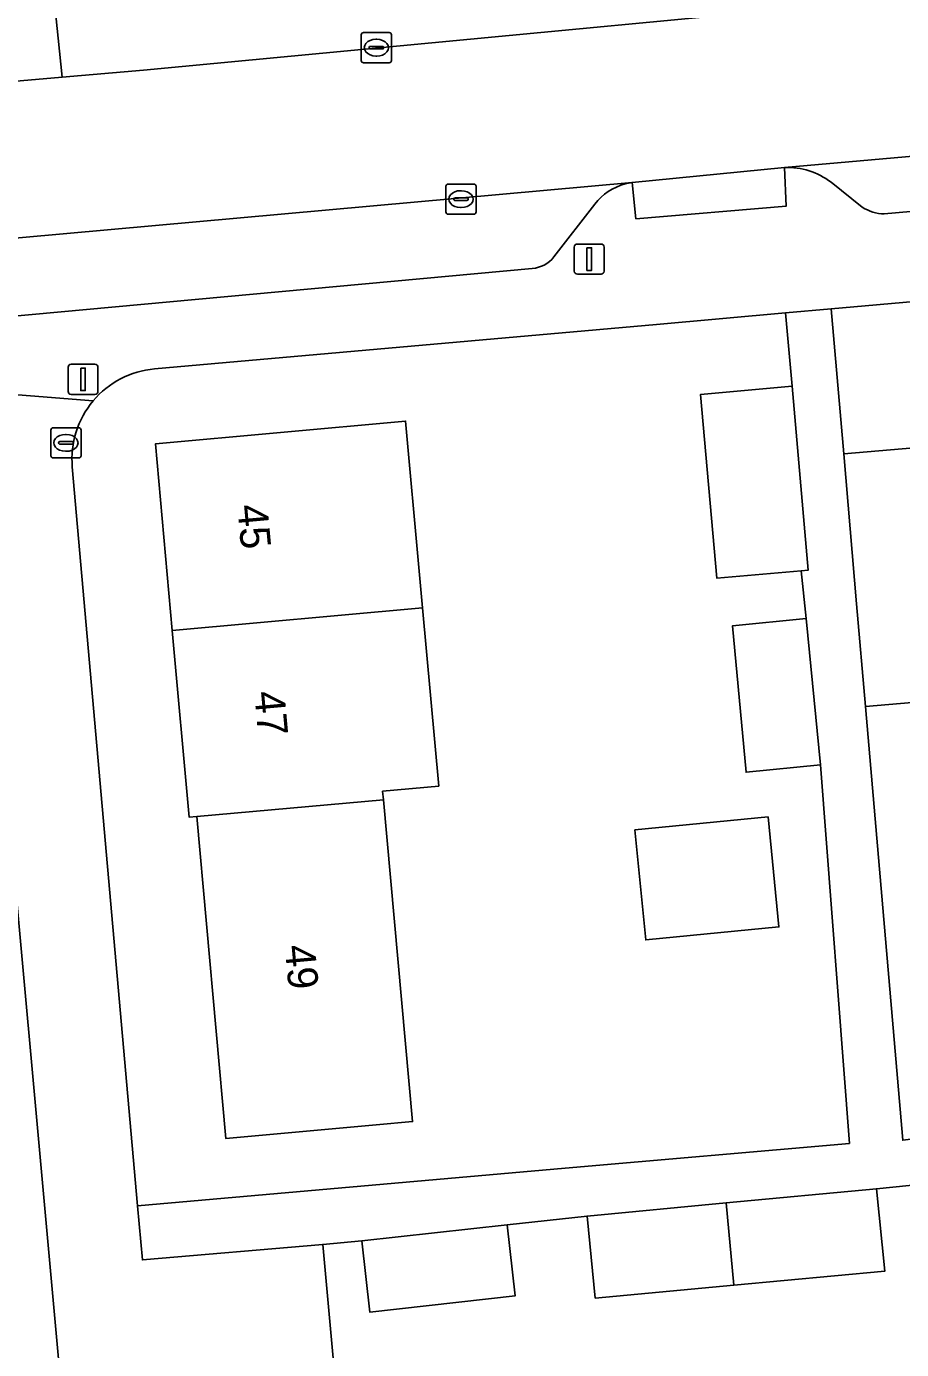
# Model space of a CAD drawing. Extents: x 160554 to 161248, y 385329 to 386506.
# Drawn here: x 160851.48 to 160880.52, y 385569.34 to 385613.21 of the extents above; entities that cross this region are included whole.
import ezdxf

# ---------------------------------------------------------------- set-up
doc = ezdxf.new("R2010")
doc.units = 0
for name, color, linetype in [('IMGEO_Erf', 7, 'Continuous'), ('IMGEO_Kolk', 7, 'Continuous'), ('IMGEO_Lichtmast', 7, 'Continuous'), ('IMGEO_Pand', 7, 'Continuous'), ('IMGEO_Pand_nummerreeks', 7, 'Continuous'), ('IMGEO_Parkeervlak_open', 7, 'Continuous'), ('IMGEO_Rijbaan_lokaal_open', 7, 'Continuous'), ('IMGEO_Voetpad_open', 7, 'Continuous')]:
    doc.layers.add(name, color=color, linetype=linetype)

msp = doc.modelspace()

# ---------------------------------------------------------------- linework, layer by layer
at = {"layer": 'IMGEO_Erf'}
for points in [[(160908.245, 385606.508), (160878.183, 385603.847), (160878.608, 385599.047), (160884.671, 385599.563)], [(160877.196, 385595.166), (160874.392, 385594.918), (160873.854, 385601.014), (160876.889, 385601.282), (160876.674, 385603.713), (160872.393, 385603.334), (160855.731, 385601.859)], [(160853.004, 385598.607), (160855.171, 385574.108), (160869.356, 385575.356), (160878.791, 385576.176), (160877.83, 385588.725), (160875.36, 385588.483), (160874.909, 385593.334), (160877.352, 385593.581), (160877.196, 385595.166)], [(160885.385, 385591.184), (160879.321, 385590.668), (160880.56, 385576.28)], [(160853.807, 385555.183), (160850.785, 385588.354)], [(160881.973, 385574.899), (160879.689, 385574.673), (160879.972, 385571.941), (160874.957, 385571.475), (160870.356, 385571.048), (160870.086, 385573.767), (160867.436, 385573.477), (160867.696, 385571.117), (160862.875, 385570.585), (160862.615, 385572.945), (160861.315, 385572.826), (160862.693, 385557.771)]]:
    msp.add_lwpolyline(points, dxfattribs=at)
for points in [[(160864.296, 385576.901), (160863.082, 385576.791), (160858.102, 385576.338), (160857.132, 385587.015), (160856.885, 385586.993), (160856.322, 385593.182), (160855.76, 385599.373), (160864.065, 385600.127), (160864.517, 385595.148), (160864.627, 385593.937), (160865.164, 385588.026), (160863.301, 385587.856), (160863.327, 385587.574)], [(160876.095, 385587.003), (160876.454, 385583.356), (160872.034, 385582.923), (160871.676, 385586.569)]]:
    msp.add_lwpolyline(points, close=True, dxfattribs=at)
for centre, radius, start, end in [((160855.994, 385598.869), 3.002, 95.0223, 140.0045), ((160855.993, 385598.87), 3.001, 140.0147, 185.0243)]:
    msp.add_arc(centre, radius, start, end, dxfattribs=at)
at = {"layer": 'IMGEO_Kolk'}
for p, q in [((160862.593, 385612.085), (160862.593, 385612.937)), ((160862.668, 385613.011), (160863.52, 385613.011)), ((160863.081, 385612.791), (160863.106, 385612.791)), ((160863.594, 385612.937), (160863.594, 385612.085)), ((160862.852, 385612.505), (160862.852, 385612.517)), ((160863.29, 385612.468), (160862.892, 385612.468)), ((160862.895, 385612.554), (160863.293, 385612.554)), ((160863.104, 385612.231), (160863.079, 385612.231)), ((160863.336, 385612.517), (160863.336, 385612.505)), ((160863.52, 385612.011), (160862.668, 385612.011)), ((160865.401, 385607.062), (160865.401, 385607.914)), ((160865.476, 385607.988), (160866.328, 385607.988)), ((160866.402, 385607.914), (160866.402, 385607.062)), ((160865.66, 385607.482), (160865.66, 385607.494)), ((160866.098, 385607.445), (160865.7, 385607.445)), ((160865.703, 385607.531), (160866.101, 385607.531)), ((160865.889, 385607.768), (160865.914, 385607.768)), ((160866.144, 385607.494), (160866.144, 385607.482)), ((160866.328, 385606.988), (160865.476, 385606.988)), ((160865.912, 385607.208), (160865.887, 385607.208)), ((160852.291, 385598.98), (160852.291, 385599.832)), ((160852.366, 385599.906), (160853.218, 385599.906)), ((160852.779, 385599.686), (160852.804, 385599.686)), ((160853.292, 385599.832), (160853.292, 385598.98)), ((160852.55, 385599.4), (160852.55, 385599.412)), ((160852.988, 385599.363), (160852.59, 385599.363)), ((160852.593, 385599.449), (160852.991, 385599.449)), ((160852.802, 385599.126), (160852.777, 385599.126)), ((160853.034, 385599.412), (160853.034, 385599.4)), ((160853.218, 385598.906), (160852.366, 385598.906))]:
    msp.add_line(p, q, dxfattribs=at)
for points in [[(160862.593, 385612.085), (160862.593, 385612.937)], [(160862.668, 385613.011), (160863.52, 385613.011)], [(160863.594, 385612.937), (160863.594, 385612.085)], [(160863.52, 385612.011), (160862.668, 385612.011)], [(160865.401, 385607.062), (160865.401, 385607.914)], [(160865.476, 385607.988), (160866.328, 385607.988)], [(160866.402, 385607.914), (160866.402, 385607.062)], [(160866.328, 385606.988), (160865.476, 385606.988)], [(160852.291, 385598.98), (160852.291, 385599.832)], [(160852.366, 385599.906), (160853.218, 385599.906)], [(160853.292, 385599.832), (160853.292, 385598.98)], [(160853.218, 385598.906), (160852.366, 385598.906)]]:
    msp.add_lwpolyline(points, dxfattribs=at)
for centre, radius, start, end in [((160862.67, 385612.935), 0.0765, 91.552, 178.448), ((160862.67, 385612.935), 0.0765, 91.552, 178.448), ((160863.518, 385612.935), 0.0765, 1.552, 88.448), ((160863.518, 385612.935), 0.0765, 1.552, 88.448), ((160862.892, 385612.514), 0.0403, 85.8775, 175.7526), ((160862.889, 385612.504), 0.0366, 178.938, 274.7102), ((160863.293, 385612.511), 0.043, 264.8664, 352.4533), ((160863.297, 385612.516), 0.0386, 1.7309, 96.639), ((160862.67, 385612.087), 0.0765, 181.552, 268.448), ((160862.67, 385612.087), 0.0765, 181.552, 268.448), ((160863.518, 385612.087), 0.0765, 271.552, 358.448), ((160863.518, 385612.087), 0.0765, 271.552, 358.448), ((160865.478, 385607.912), 0.0765, 91.552, 178.448), ((160865.478, 385607.912), 0.0765, 91.552, 178.448), ((160866.326, 385607.912), 0.0765, 1.552, 88.448), ((160866.326, 385607.912), 0.0765, 1.552, 88.448), ((160865.7, 385607.491), 0.0403, 85.8775, 175.7526), ((160865.697, 385607.481), 0.0366, 178.938, 274.7102), ((160866.101, 385607.488), 0.043, 264.8664, 352.4533), ((160866.105, 385607.493), 0.0386, 1.7309, 96.639), ((160865.478, 385607.064), 0.0765, 181.552, 268.448), ((160865.478, 385607.064), 0.0765, 181.552, 268.448), ((160866.326, 385607.064), 0.0765, 271.552, 358.448), ((160866.326, 385607.064), 0.0765, 271.552, 358.448), ((160852.368, 385599.83), 0.0765, 91.552, 178.448), ((160852.368, 385599.83), 0.0765, 91.552, 178.448), ((160853.216, 385599.83), 0.0765, 1.552, 88.448), ((160853.216, 385599.83), 0.0765, 1.552, 88.448), ((160852.59, 385599.409), 0.0403, 85.8775, 175.7526), ((160852.587, 385599.399), 0.0366, 178.938, 274.7102), ((160852.991, 385599.406), 0.043, 264.8664, 352.4533), ((160852.995, 385599.411), 0.0386, 1.7309, 96.639), ((160852.368, 385598.982), 0.0765, 181.552, 268.448), ((160852.368, 385598.982), 0.0765, 181.552, 268.448), ((160853.216, 385598.982), 0.0765, 271.552, 358.448), ((160853.216, 385598.982), 0.0765, 271.552, 358.448)]:
    msp.add_arc(centre, radius, start, end, dxfattribs=at)
for centre, major_axis, ratio, start_param, end_param in [((160863.08, 385612.511), (-0.387, 0.002), 0.722429, 4.712389, 7.853982), ((160863.105, 385612.511), (-0.39, 0.002), 0.717154, 1.570796, 4.712389), ((160865.888, 385607.488), (-0.387, 0.002), 0.722429, 4.712389, 7.853982), ((160865.913, 385607.488), (-0.39, 0.002), 0.717154, 1.570796, 4.712389), ((160852.778, 385599.406), (-0.387, 0.002), 0.722429, 4.712389, 7.853982), ((160852.803, 385599.406), (-0.39, 0.002), 0.717154, 1.570796, 4.712389)]:
    msp.add_ellipse(centre, major_axis=major_axis, ratio=ratio, start_param=start_param, end_param=end_param, dxfattribs=at)
at = {"layer": 'IMGEO_Lichtmast'}
for p, q in [((160869.663, 385605.1), (160869.663, 385605.9)), ((160869.663, 385605.9), (160869.663, 385605.1)), ((160869.763, 385606), (160870.553, 385606)), ((160870.553, 385606), (160869.763, 385606)), ((160870.653, 385605.9), (160870.653, 385605.1)), ((160870.653, 385605.1), (160870.653, 385605.9)), ((160870.553, 385605), (160869.763, 385605)), ((160869.763, 385605), (160870.553, 385605)), ((160852.864, 385601.113), (160852.864, 385601.913)), ((160852.864, 385601.913), (160852.864, 385601.113)), ((160852.964, 385602.013), (160853.754, 385602.013)), ((160853.754, 385602.013), (160852.964, 385602.013)), ((160853.854, 385601.913), (160853.854, 385601.113)), ((160853.854, 385601.113), (160853.854, 385601.913)), ((160853.754, 385601.013), (160852.964, 385601.013)), ((160852.964, 385601.013), (160853.754, 385601.013))]:
    msp.add_line(p, q, dxfattribs=at)
for points in [[(160870.083, 385605.875), (160870.233, 385605.875), (160870.233, 385605.125), (160870.083, 385605.125), (160870.083, 385605.875)], [(160853.284, 385601.888), (160853.434, 385601.888), (160853.434, 385601.138), (160853.284, 385601.138), (160853.284, 385601.888)]]:
    msp.add_lwpolyline(points, dxfattribs=at)
for centre, start, end in [((160869.763, 385605.9), 90, 180), ((160869.763, 385605.9), 90, 180), ((160870.553, 385605.9), 0, 90), ((160870.553, 385605.9), 360, 90), ((160869.763, 385605.1), 180, 270), ((160869.763, 385605.1), 180, 270), ((160870.553, 385605.1), 270, 0), ((160870.553, 385605.1), 270, 0), ((160852.964, 385601.913), 90, 180), ((160852.964, 385601.913), 90, 180), ((160853.754, 385601.913), 0, 90), ((160853.754, 385601.913), 360, 90), ((160852.964, 385601.113), 180, 270), ((160852.964, 385601.113), 180, 270), ((160853.754, 385601.113), 270, 0), ((160853.754, 385601.113), 270, 0)]:
    msp.add_arc(centre, 0.1, start, end, dxfattribs=at)
at = {"layer": 'IMGEO_Pand'}
for points in [[(160876.889, 385601.282), (160873.854, 385601.014), (160874.392, 385594.918), (160877.196, 385595.166), (160877.427, 385595.186)], [(160864.627, 385593.937), (160864.517, 385595.148), (160864.065, 385600.127), (160855.76, 385599.373), (160856.322, 385593.182)], [(160884.671, 385599.563), (160878.608, 385599.047), (160879.032, 385594.066), (160879.321, 385590.668), (160885.385, 385591.184)], [(160864.627, 385593.937), (160856.322, 385593.182), (160856.885, 385586.993), (160857.132, 385587.015), (160863.327, 385587.574), (160863.301, 385587.856), (160865.164, 385588.026)], [(160877.352, 385593.581), (160874.909, 385593.334), (160875.36, 385588.483), (160877.83, 385588.725)], [(160863.327, 385587.574), (160857.132, 385587.015), (160858.102, 385576.338), (160863.082, 385576.791), (160864.296, 385576.901)], [(160871.676, 385586.569), (160872.034, 385582.923), (160876.454, 385583.356), (160876.095, 385587.003)], [(160874.957, 385571.475), (160879.972, 385571.941), (160879.689, 385574.673), (160874.702, 385574.202)], [(160874.702, 385574.202), (160870.086, 385573.767), (160870.356, 385571.048), (160874.957, 385571.475)], [(160862.875, 385570.585), (160867.696, 385571.117), (160867.436, 385573.477), (160862.615, 385572.945)]]:
    msp.add_lwpolyline(points, close=True, dxfattribs=at)
at = {"layer": 'IMGEO_Parkeervlak_open'}
for points in [[(160905.88, 385611.113), (160876.64, 385608.535)], [(160879.95, 385606.996), (160902.975, 385609.049)], [(160871.354, 385607.991), (160871.578, 385608.044), (160842.631, 385605.434)], [(160878.183, 385608.051), (160879.218, 385607.22)], [(160868.984, 385605.57), (160870.346, 385607.317)], [(160846.391, 385603.199), (160846.975, 385603.229), (160868.265, 385605.193)]]:
    msp.add_lwpolyline(points, dxfattribs=at)
for centre, radius, start, end in [((160876.737, 385606.141), 2.396, 52.8589, 92.3105), ((160871.785, 385606.256), 1.788, 103.9441, 143.5932), ((160880.003, 385608.477), 1.482, 238.0154, 267.9553), ((160868.207, 385606.177), 0.986, 273.3559, 321.9837)]:
    msp.add_arc(centre, radius, start, end, dxfattribs=at)
at = {"layer": 'IMGEO_Rijbaan_lokaal_open'}
msp.add_lwpolyline([(160871.578, 385608.044), (160876.64, 385608.535), (160905.88, 385611.113), (160907.275, 385611.259), (160906.791, 385616.603), (160886.64, 385614.737), (160855.368, 385611.764), (160852.666, 385611.53), (160831.052, 385609.652), (160829.274, 385609.552), (160812.695, 385608.034), (160812.515, 385608.009), (160812.984, 385602.775), (160842.289, 385605.408), (160842.631, 385605.434)], close=True, dxfattribs=at)
at = {"layer": 'IMGEO_Voetpad_open'}
for points in [[(160849.453, 385619.331), (160844.766, 385618.807), (160844.463, 385618.859), (160844.032, 385618.825), (160840.182, 385618.492), (160839.297, 385618.416), (160836.165, 385618.147), (160833.286, 385617.9), (160830.449, 385617.656), (160831.052, 385609.652), (160852.666, 385611.53), (160852.367, 385614.453), (160851.846, 385619.534)], [(160871.578, 385608.044), (160871.705, 385606.84), (160876.69, 385607.255), (160876.64, 385608.535)], [(160879.032, 385594.066), (160878.608, 385599.047), (160878.183, 385603.847), (160876.674, 385603.713), (160876.889, 385601.282), (160877.427, 385595.186), (160877.196, 385595.166), (160877.352, 385593.581), (160877.83, 385588.725), (160878.791, 385576.176), (160869.356, 385575.356), (160855.171, 385574.108), (160855.33, 385572.311), (160861.315, 385572.826), (160862.615, 385572.945), (160867.436, 385573.477), (160870.086, 385573.767), (160874.702, 385574.202), (160879.689, 385574.673), (160881.973, 385574.899), (160881.898, 385575.713), (160881.831, 385576.441), (160880.56, 385576.28), (160879.321, 385590.668)]]:
    msp.add_lwpolyline(points, close=True, dxfattribs=at)
for points in [[(160885.887, 385617.46), (160852.367, 385614.453), (160852.666, 385611.53), (160855.368, 385611.764), (160886.64, 385614.737), (160886.36, 385618.018)], [(160902.975, 385609.049), (160879.95, 385606.996)], [(160876.64, 385608.535), (160876.69, 385607.255), (160871.705, 385606.84), (160871.578, 385608.044), (160871.354, 385607.991)], [(160879.218, 385607.22), (160878.183, 385608.051)], [(160870.346, 385607.317), (160868.984, 385605.57)], [(160855.731, 385601.859), (160872.393, 385603.334), (160876.674, 385603.713), (160878.183, 385603.847), (160908.245, 385606.508)], [(160868.265, 385605.193), (160846.975, 385603.229)], [(160853.694, 385600.798), (160849.53, 385601.127), (160849.947, 385597.294), (160849.969, 385597.157), (160850.785, 385588.354), (160853.807, 385555.183), (160850.708, 385554.964), (160850.795, 385554.015), (160853.308, 385554.158), (160860.81, 385554.801), (160862.922, 385554.982), (160863.436, 385548.992), (160864.993, 385549.134), (160864.477, 385554.802), (160864.3, 385554.785), (160864.268, 385555.123), (160864.008, 385557.909), (160862.693, 385557.771), (160861.315, 385572.826)], [(160849.53, 385601.127), (160853.694, 385600.798)], [(160861.315, 385572.826), (160855.33, 385572.311), (160855.171, 385574.108), (160853.004, 385598.607)]]:
    msp.add_lwpolyline(points, dxfattribs=at)
for centre, radius, start, end in [((160876.737, 385606.141), 2.396, 52.8589, 92.3105), ((160871.785, 385606.256), 1.788, 103.9441, 143.5932), ((160880.003, 385608.477), 1.482, 238.0154, 267.9553), ((160868.207, 385606.177), 0.986, 273.3559, 321.9837), ((160855.994, 385598.869), 3.002, 95.0223, 140.0045), ((160855.993, 385598.87), 3.001, 140.0147, 185.0243)]:
    msp.add_arc(centre, radius, start, end, dxfattribs=at)

# ---------------------------------------------------------------- texts
at = {"layer": 'IMGEO_Pand_nummerreeks'}
for s, rotation, p in [('45', 275.1915, (160858.476, 385597.329)), ('47', 275.1908, (160859.039, 385591.138)), ('49', 275.1908, (160860.052, 385582.727))]:
    msp.add_text(s, height=1, rotation=rotation, dxfattribs=at).set_placement(p)

doc.saveas('drawing.dxf')
